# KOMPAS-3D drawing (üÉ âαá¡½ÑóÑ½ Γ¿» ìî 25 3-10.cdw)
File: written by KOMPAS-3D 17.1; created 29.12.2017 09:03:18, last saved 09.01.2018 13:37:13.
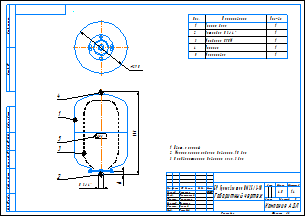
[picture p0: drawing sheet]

Sheet 1: A3, landscape, title-block layout from C:\Лощинин\GRAPHIC.LYT style 1

Title block, sheet 1: name: БР Гранлевел тип НМ 25/3-10 / Габаритный чертеж; mass: 4,0; sheets: 1; sheet format: A3; stored path: K:\АП\20_PKO\02_Насосное направление\Разработка\04_Проекты разные\Баки\КД действующая\Баки Flexcon R\Компас\Чертежи\БР Гранлевел тип НМ 25 1,5-6.cdw; drawn by: Лощинин; checked by: Хантимеров; drawn by, date: 29.12.2017

Views: Вид 1, Снизу
Referenced files in \\Fsk1\files\АП\20_PKO\02_Насосное направление\Разработка\04_Проекты разные\Баки\КД действующая\Баки Flexcon R\Компас\: 25 литров.a3d
Referenced files in C:\Лощинин\: GRAPHIC.LYT
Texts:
  IvAn
  ADL
  БР Гранлевел тип НМ 25/1,5-6
  Цвет: красный
  Максимальное рабочее давление: 10 бар
  Предварительное давление газа: 3 бар
  ACAD_ISO03W100_RGB_223_127_255_SC_1_THICK_0.05
  ACAD_ISO03W100_RGB_223_127_255_SC_0.063_THICK_0.05
  Лит-Масса-Масштаб
  Материал-Предприятие
  Масштаб
  Изм.
  Лист
  № докум.
  Подп.
  Дата
  Лит.
  Разраб.
  Пров.
  Т.контр.
  Курлыкина
  Листов
  Нач.отд.
  Щетинин
  Н.контр.
  Долгов
  Утв.
  Рашидов
  Компания АДЛ
  Изменение
  Номер документа
  Подпись
  Обозначение документа
  Наименование изделия
  Масса изделия по ГОСТ 2.109-73
  Порядковый номер листа
  Общее количество листов в документе
  Характер работы, выполненной лицом, подписавшим документ
  Наименование или индекс предприятия, выпускающего документ
  Инв. № подл.
  Подп. и дата
  Взам. инв. №
  Инв. № дубл.
  Инвентарный номер подлинника по ГОСТ 2.501-68
  Подпись принявшего подлинник в отдел технической документации
  Инвентарный номер подлинника, взамен которого выпущен данный подлинник
  Инвентарный номер дубликата по ГОСТ 2.502-68
  Подпись принявшего дубликат в отдел технической документации
  Справ. №
  Перв. примен.
  Обозначение документа, взамен или на основании которого выпущен данный документ
  Обозначение документа, в котором впервые записан данный документ
  Подпись лица, копировавшего чертеж
  Обозначение формата листа
Dimensions and other numbers on the sheet: 290; 1:4; 1; 4,0; 29.12.2017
